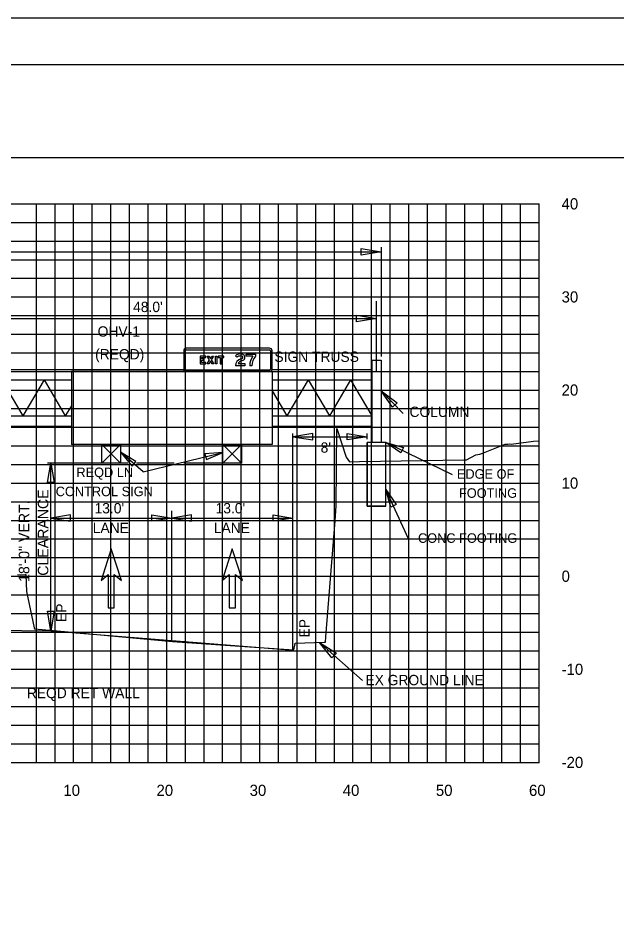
# Model space of a CAD drawing. Extents: x 2193008 to 2198143, y 1236112 to 1237864.
# Drawn here: x 2195392.7 to 2195457, y 1237239.8 to 1237338 of the extents above; entities that cross this region are included whole.
import ezdxf

# ---------------------------------------------------------------- set-up
doc = ezdxf.new("R2010")
doc.units = 0
for name, color, linetype in [('10', 7, 'Continuous'), ('3', 7, 'Continuous'), ('31', 7, 'Continuous'), ('60', 7, 'Continuous'), ('CL-CNST', 7, 'Continuous'), ('GSBWFILL', 7, 'Continuous'), ('GSCOLORFILL', 7, 'Continuous'), ('GSDIMS', 7, 'Continuous'), ('GSOUTLINE', 7, 'Continuous'), ('Level 1', 7, 'Continuous'), ('Level 28', 7, 'Continuous'), ('Level 55', 7, 'Continuous'), ('Level 62', 7, 'Continuous'), ('M-ROADS', 7, 'Continuous'), ('SHT-BDR', 7, 'Continuous'), ('SHT-BNDRY', 7, 'Continuous'), ('V7Level1', 7, 'Continuous')]:
    doc.layers.add(name, color=color, linetype=linetype)

msp = doc.modelspace()

# ---------------------------------------------------------------- linework, layer by layer
msp.add_line((2195431.149, 1237300.108), (2195431.149, 1237307.648))
at = {"layer": '3'}
for p, q in [((2195345.592, 1237312.95), (2195431.649, 1237312.95)), ((2195431.649, 1237313.437), (2195431.649, 1237301.72)), ((2195430.649, 1237301.295), (2195430.649, 1237292.478)), ((2195431.649, 1237301.295), (2195431.649, 1237292.478)), ((2195434.018, 1237295.573), (2195431.649, 1237298.016)), ((2195422.173, 1237270.174), (2195422.173, 1237293.438)), ((2195430.149, 1237292.816), (2195430.149, 1237293.438)), ((2195432.173, 1237292.478), (2195430.149, 1237292.478)), ((2195430.149, 1237285.625), (2195430.149, 1237292.478)), ((2195439.311, 1237289.012), (2195432.173, 1237292.478)), ((2195432.173, 1237285.625), (2195432.173, 1237292.478)), ((2195406.108, 1237289.3), (2195403.67, 1237291.448)), ((2195406.108, 1237289.3), (2195414.672, 1237291.412)), ((2195396.169, 1237272.254), (2195396.169, 1237290.254)), ((2195434.599, 1237282.115), (2195432.173, 1237287.417)), ((2195432.173, 1237285.625), (2195430.149, 1237285.625)), ((2195409.171, 1237271.214), (2195409.171, 1237285.142)), ((2195429.639, 1237266.891), (2195425.039, 1237270.994))]:
    msp.add_line(p, q, dxfattribs=at)
at = {"layer": '60'}
for p, q in [((2195448.632, 1237258.106), (2195448.632, 1237318.106)), ((2195328.632, 1237258.106), (2195448.632, 1237258.106)), ((2195398.632, 1237258.046), (2195398.632, 1237258.106)), ((2195408.632, 1237258.046), (2195408.632, 1237258.106)), ((2195418.632, 1237258.046), (2195418.632, 1237258.106)), ((2195428.632, 1237258.046), (2195428.632, 1237258.106)), ((2195438.632, 1237258.046), (2195438.632, 1237258.106)), ((2195448.632, 1237258.046), (2195448.632, 1237258.106))]:
    msp.add_line(p, q, dxfattribs=at)
at = {"layer": 'CL-CNST'}
msp.add_lwpolyline([(2195389.882, 1237272.317), (2195396.169, 1237272.254), (2195409.171, 1237271.214), (2195422.259, 1237270.167)], dxfattribs=at)
at = {"layer": 'GSBWFILL'}
msp.add_line((2195417.766, 1237300.716), (2195417.541, 1237300.716), dxfattribs=at)
for points in [[(2195417.872, 1237301.74), (2195417.166, 1237301.74), (2195417.166, 1237301.965), (2195418.178, 1237301.965), (2195418.178, 1237301.758)], [(2195416.163, 1237301.624), (2195416.017, 1237301.795)], [(2195416.292, 1237300.941), (2195417.029, 1237300.941), (2195417.029, 1237300.716), (2195416.017, 1237300.716)]]:
    msp.add_lwpolyline(points, dxfattribs=at)
for points in [[(2195412.845, 1237301.074), (2195412.371, 1237301.074), (2195412.371, 1237301.298), (2195412.617, 1237301.298), (2195412.617, 1237301.447), (2195412.371, 1237301.447), (2195412.371, 1237301.607), (2195412.833, 1237301.607), (2195412.833, 1237301.756), (2195412.221, 1237301.756), (2195412.221, 1237300.924), (2195412.845, 1237300.924)], [(2195413.509, 1237300.924), (2195413.324, 1237301.219), (2195413.139, 1237300.924), (2195412.962, 1237300.924), (2195413.236, 1237301.36), (2195412.987, 1237301.756), (2195413.164, 1237301.756), (2195413.324, 1237301.501), (2195413.484, 1237301.756), (2195413.661, 1237301.756), (2195413.413, 1237301.36), (2195413.686, 1237300.924)], [(2195413.853, 1237300.924), (2195413.853, 1237301.756), (2195414.003, 1237301.756), (2195414.003, 1237300.924)], [(2195414.144, 1237301.607), (2195414.381, 1237301.607), (2195414.381, 1237300.924), (2195414.531, 1237300.924), (2195414.531, 1237301.607), (2195414.769, 1237301.607), (2195414.769, 1237301.756), (2195414.144, 1237301.756)]]:
    msp.add_lwpolyline(points, close=True, dxfattribs=at)
for radius, start in [(1.748, 144.14653), (1.523, 136.84518)]:
    msp.add_arc((2195419.289, 1237300.716), radius, start, 180, dxfattribs=at)
for centre, major_axis, start_param, end_param in [((2195416.539, 1237301.181), (0, 0.806), 0, 0.70376), ((2195416.539, 1237301.197), (0, 0.789), 6.02311, 6.283185), ((2195416.624, 1237301.517), (0, 0.458), 5.706931, 6.02311), ((2195416.771, 1237300.716), (0, 0.754), 0.25053, 1.570796), ((2195416.539, 1237301.181), (0, 0.581), 0, 0.70376), ((2195416.771, 1237300.716), (0, 0.529), 0.25053, 1.132058), ((2195416.539, 1237301.197), (0, 0.565), 6.02311, 6.283185), ((2195416.41, 1237302.128), (0, 0.704), 3.392123, 3.626327), ((2195416.41, 1237302.128), (0, 0.928), 3.392123, 3.626327), ((2195416.624, 1237301.517), (0, 0.233), 5.706931, 6.02311), ((2195416.68, 1237301.615), (0, 0.124), 3.626327, 4.712389), ((2195416.687, 1237301.615), (0, 0.117), 4.712389, 5.706931), ((2195416.68, 1237301.615), (0, 0.349), 3.626327, 4.712389), ((2195416.687, 1237301.615), (0, 0.341), 4.712389, 5.706931)]:
    msp.add_ellipse(centre, major_axis=major_axis, ratio=0.999994, start_param=start_param, end_param=end_param, dxfattribs=at)
at = {"layer": 'GSCOLORFILL'}
for p, q in [((2195410.452, 1237302.322), (2195410.452, 1237300.358)), ((2195410.619, 1237300.358), (2195410.619, 1237302.322)), ((2195419.68, 1237302.593), (2195410.723, 1237302.593)), ((2195410.723, 1237302.427), (2195419.68, 1237302.427)), ((2195419.784, 1237302.322), (2195419.784, 1237300.358)), ((2195419.951, 1237300.358), (2195419.951, 1237302.322)), ((2195410.723, 1237300.087), (2195410.723, 1237300.254)), ((2195419.68, 1237300.254), (2195410.724, 1237300.254)), ((2195410.724, 1237300.254), (2195410.724, 1237300.087)), ((2195410.724, 1237300.087), (2195419.68, 1237300.087)), ((2195417.766, 1237300.716), (2195417.541, 1237300.716))]:
    msp.add_line(p, q, dxfattribs=at)
for points in [[(2195417.872, 1237301.74), (2195417.166, 1237301.74), (2195417.166, 1237301.965), (2195418.178, 1237301.965), (2195418.178, 1237301.758)], [(2195416.163, 1237301.624), (2195416.017, 1237301.795)], [(2195416.292, 1237300.941), (2195417.029, 1237300.941), (2195417.029, 1237300.716), (2195416.017, 1237300.716)]]:
    msp.add_lwpolyline(points, dxfattribs=at)
for points in [[(2195412.845, 1237301.074), (2195412.371, 1237301.074), (2195412.371, 1237301.298), (2195412.617, 1237301.298), (2195412.617, 1237301.447), (2195412.371, 1237301.447), (2195412.371, 1237301.607), (2195412.833, 1237301.607), (2195412.833, 1237301.756), (2195412.221, 1237301.756), (2195412.221, 1237300.924), (2195412.845, 1237300.924)], [(2195413.509, 1237300.924), (2195413.324, 1237301.219), (2195413.139, 1237300.924), (2195412.962, 1237300.924), (2195413.236, 1237301.36), (2195412.987, 1237301.756), (2195413.164, 1237301.756), (2195413.324, 1237301.501), (2195413.484, 1237301.756), (2195413.661, 1237301.756), (2195413.413, 1237301.36), (2195413.686, 1237300.924)], [(2195413.853, 1237300.924), (2195413.853, 1237301.756), (2195414.003, 1237301.756), (2195414.003, 1237300.924)], [(2195414.144, 1237301.607), (2195414.381, 1237301.607), (2195414.381, 1237300.924), (2195414.531, 1237300.924), (2195414.531, 1237301.607), (2195414.769, 1237301.607), (2195414.769, 1237301.756), (2195414.144, 1237301.756)]]:
    msp.add_lwpolyline(points, close=True, dxfattribs=at)
for centre, radius, start, end in [((2195410.723, 1237302.322), 0.271, 90, 180), ((2195410.723, 1237302.322), 0.104, 90, 180), ((2195419.68, 1237302.322), 0.271, 0, 90), ((2195419.68, 1237302.322), 0.104, 0, 90), ((2195419.289, 1237300.716), 1.748, 144.14653, 180), ((2195419.289, 1237300.716), 1.523, 136.84518, 180), ((2195410.723, 1237300.358), 0.271, 180, 270), ((2195410.723, 1237300.358), 0.104, 180, 270), ((2195419.68, 1237300.358), 0.271, 270, 0), ((2195419.68, 1237300.358), 0.104, 270, 0)]:
    msp.add_arc(centre, radius, start, end, dxfattribs=at)
for centre, major_axis, start_param, end_param in [((2195416.539, 1237301.181), (0, 0.806), 0, 0.70376), ((2195416.539, 1237301.197), (0, 0.789), 6.02311, 6.283185), ((2195416.624, 1237301.517), (0, 0.458), 5.706931, 6.02311), ((2195416.771, 1237300.716), (0, 0.754), 0.25053, 1.570796), ((2195416.539, 1237301.181), (0, 0.581), 0, 0.70376), ((2195416.771, 1237300.716), (0, 0.529), 0.25053, 1.132058), ((2195416.539, 1237301.197), (0, 0.565), 6.02311, 6.283185), ((2195416.41, 1237302.128), (0, 0.704), 3.392123, 3.626327), ((2195416.41, 1237302.128), (0, 0.928), 3.392123, 3.626327), ((2195416.624, 1237301.517), (0, 0.233), 5.706931, 6.02311), ((2195416.68, 1237301.615), (0, 0.124), 3.626327, 4.712389), ((2195416.687, 1237301.615), (0, 0.117), 4.712389, 5.706931), ((2195416.68, 1237301.615), (0, 0.349), 3.626327, 4.712389), ((2195416.687, 1237301.615), (0, 0.341), 4.712389, 5.706931)]:
    msp.add_ellipse(centre, major_axis=major_axis, ratio=0.999994, start_param=start_param, end_param=end_param, dxfattribs=at)
at = {"layer": 'GSDIMS'}
for p, q in [((2195383.079, 1237305.791), (2195431.143, 1237305.791)), ((2195430.649, 1237301.295), (2195431.649, 1237301.295)), ((2195383.079, 1237300.295), (2195410.452, 1237300.295)), ((2195398.387, 1237300.087), (2195398.387, 1237292.254)), ((2195419.951, 1237300.087), (2195398.387, 1237300.087)), ((2195419.951, 1237300.295), (2195430.649, 1237300.295)), ((2195419.951, 1237300.087), (2195419.951, 1237292.254)), ((2195383.079, 1237299.184), (2195398.387, 1237299.184)), ((2195390.903, 1237299.184), (2195393.181, 1237295.322)), ((2195395.46, 1237299.184), (2195393.181, 1237295.322)), ((2195395.46, 1237299.184), (2195397.738, 1237295.322)), ((2195419.951, 1237299.184), (2195430.649, 1237299.184)), ((2195423.813, 1237299.184), (2195421.534, 1237295.322)), ((2195423.813, 1237299.184), (2195426.092, 1237295.322)), ((2195428.37, 1237299.184), (2195426.092, 1237295.322)), ((2195428.37, 1237299.184), (2195430.649, 1237295.322)), ((2195419.951, 1237298.006), (2195421.534, 1237295.322)), ((2195398.387, 1237296.421), (2195397.738, 1237295.322)), ((2195383.079, 1237295.322), (2195398.387, 1237295.322)), ((2195419.951, 1237295.322), (2195430.649, 1237295.322)), ((2195383.058, 1237294.211), (2195398.387, 1237294.211)), ((2195419.951, 1237294.211), (2195430.649, 1237294.211)), ((2195422.177, 1237293.091), (2195430.149, 1237293.091)), ((2195419.951, 1237292.254), (2195398.387, 1237292.254)), ((2195404.441, 1237290.254), (2195395.814, 1237290.254)), ((2195409.415, 1237290.254), (2195405.378, 1237290.254)), ((2195414.672, 1237290.254), (2195410.467, 1237290.254)), ((2195396.169, 1237284.354), (2195409.171, 1237284.354)), ((2195409.171, 1237284.354), (2195422.173, 1237284.354))]:
    msp.add_line(p, q, dxfattribs=at)
for points in [[(2195431.649, 1237312.95), (2195429.52, 1237312.603), (2195429.52, 1237313.298)], [(2195431.143, 1237305.791), (2195429.014, 1237305.444), (2195429.014, 1237306.139)], [(2195431.649, 1237298.016), (2195433.371, 1237296.744), (2195432.857, 1237296.266)], [(2195422.177, 1237293.091), (2195424.305, 1237292.743), (2195424.305, 1237293.438)], [(2195430.149, 1237293.091), (2195428.02, 1237292.743), (2195428.02, 1237293.438)], [(2195432.173, 1237292.478), (2195434.042, 1237291.926), (2195433.762, 1237291.35)], [(2195403.67, 1237291.448), (2195404.9, 1237289.937), (2195405.324, 1237290.418)], [(2195414.672, 1237291.412), (2195412.729, 1237291.263), (2195412.883, 1237290.641)], [(2195396.169, 1237290.254), (2195396.524, 1237288.171), (2195395.814, 1237288.171)], [(2195432.173, 1237287.417), (2195433.264, 1237285.802), (2195432.682, 1237285.536)], [(2195396.169, 1237284.354), (2195398.297, 1237284.006), (2195398.297, 1237284.701)], [(2195409.171, 1237284.354), (2195407.043, 1237284.006), (2195407.043, 1237284.701)], [(2195409.171, 1237284.354), (2195411.299, 1237284.006), (2195411.299, 1237284.701)], [(2195422.173, 1237284.354), (2195420.045, 1237284.006), (2195420.045, 1237284.701)], [(2195396.169, 1237272.254), (2195395.814, 1237274.337), (2195396.524, 1237274.337)], [(2195425.039, 1237270.994), (2195426.849, 1237269.85), (2195426.37, 1237269.336)]]:
    msp.add_lwpolyline(points, close=True, dxfattribs=at)
at = {"layer": 'GSOUTLINE'}
msp.add_line((2195417.766, 1237300.716), (2195417.541, 1237300.716), dxfattribs=at)
for points in [[(2195417.872, 1237301.74), (2195417.166, 1237301.74), (2195417.166, 1237301.965), (2195418.178, 1237301.965), (2195418.178, 1237301.758)], [(2195416.163, 1237301.624), (2195416.017, 1237301.795)], [(2195416.292, 1237300.941), (2195417.029, 1237300.941), (2195417.029, 1237300.716), (2195416.017, 1237300.716)]]:
    msp.add_lwpolyline(points, dxfattribs=at)
for points in [[(2195412.845, 1237301.074), (2195412.371, 1237301.074), (2195412.371, 1237301.298), (2195412.617, 1237301.298), (2195412.617, 1237301.447), (2195412.371, 1237301.447), (2195412.371, 1237301.607), (2195412.833, 1237301.607), (2195412.833, 1237301.756), (2195412.221, 1237301.756), (2195412.221, 1237300.924), (2195412.845, 1237300.924)], [(2195413.509, 1237300.924), (2195413.324, 1237301.219), (2195413.139, 1237300.924), (2195412.962, 1237300.924), (2195413.236, 1237301.36), (2195412.987, 1237301.756), (2195413.164, 1237301.756), (2195413.324, 1237301.501), (2195413.484, 1237301.756), (2195413.661, 1237301.756), (2195413.413, 1237301.36), (2195413.686, 1237300.924)], [(2195413.853, 1237300.924), (2195413.853, 1237301.756), (2195414.003, 1237301.756), (2195414.003, 1237300.924)], [(2195414.144, 1237301.607), (2195414.381, 1237301.607), (2195414.381, 1237300.924), (2195414.531, 1237300.924), (2195414.531, 1237301.607), (2195414.769, 1237301.607), (2195414.769, 1237301.756), (2195414.144, 1237301.756)]]:
    msp.add_lwpolyline(points, close=True, dxfattribs=at)
for radius, start in [(1.748, 144.14653), (1.523, 136.84518)]:
    msp.add_arc((2195419.289, 1237300.716), radius, start, 180, dxfattribs=at)
for centre, major_axis, start_param, end_param in [((2195416.539, 1237301.181), (0, 0.806), 0, 0.70376), ((2195416.539, 1237301.197), (0, 0.789), 6.02311, 6.283185), ((2195416.624, 1237301.517), (0, 0.458), 5.706931, 6.02311), ((2195416.771, 1237300.716), (0, 0.754), 0.25053, 1.570796), ((2195416.539, 1237301.181), (0, 0.581), 0, 0.70376), ((2195416.771, 1237300.716), (0, 0.529), 0.25053, 1.132058), ((2195416.539, 1237301.197), (0, 0.565), 6.02311, 6.283185), ((2195416.41, 1237302.128), (0, 0.704), 3.392123, 3.626327), ((2195416.41, 1237302.128), (0, 0.928), 3.392123, 3.626327), ((2195416.624, 1237301.517), (0, 0.233), 5.706931, 6.02311), ((2195416.68, 1237301.615), (0, 0.124), 3.626327, 4.712389), ((2195416.687, 1237301.615), (0, 0.117), 4.712389, 5.706931), ((2195416.68, 1237301.615), (0, 0.349), 3.626327, 4.712389), ((2195416.687, 1237301.615), (0, 0.341), 4.712389, 5.706931)]:
    msp.add_ellipse(centre, major_axis=major_axis, ratio=0.999994, start_param=start_param, end_param=end_param, dxfattribs=at)
at = {"layer": 'Level 1'}
for p, q in [((2195401.67, 1237292.254), (2195403.67, 1237290.254)), ((2195403.67, 1237292.254), (2195401.67, 1237290.254)), ((2195414.672, 1237292.254), (2195416.672, 1237290.254)), ((2195414.672, 1237290.254), (2195416.672, 1237292.254))]:
    msp.add_line(p, q, dxfattribs=at)
for points in [[(2195401.67, 1237292.254), (2195403.67, 1237292.254), (2195403.67, 1237290.254), (2195401.67, 1237290.254)], [(2195414.672, 1237292.254), (2195416.672, 1237292.254), (2195416.672, 1237290.254), (2195414.672, 1237290.254)]]:
    msp.add_lwpolyline(points, close=True, dxfattribs=at)
at = {"layer": 'Level 28'}
for p, q in [((2195402.67, 1237281.044), (2195401.581, 1237277.646)), ((2195403.759, 1237277.646), (2195402.67, 1237281.044)), ((2195415.672, 1237281.044), (2195414.583, 1237277.646)), ((2195416.761, 1237277.646), (2195415.672, 1237281.044)), ((2195401.581, 1237277.646), (2195402.343, 1237278.285)), ((2195402.343, 1237278.285), (2195402.343, 1237274.714)), ((2195402.997, 1237274.714), (2195402.997, 1237278.285)), ((2195402.997, 1237278.285), (2195403.759, 1237277.646)), ((2195414.583, 1237277.646), (2195415.345, 1237278.285)), ((2195415.345, 1237278.285), (2195415.345, 1237274.714)), ((2195415.999, 1237274.714), (2195415.999, 1237278.285)), ((2195415.999, 1237278.285), (2195416.761, 1237277.646)), ((2195402.343, 1237274.714), (2195402.997, 1237274.714)), ((2195415.345, 1237274.714), (2195415.999, 1237274.714))]:
    msp.add_line(p, q, dxfattribs=at)
at = {"layer": 'Level 62'}
for p, q in [((2195328.632, 1237318.106), (2195448.632, 1237318.106)), ((2195394.632, 1237258.106), (2195394.632, 1237318.106)), ((2195396.632, 1237258.106), (2195396.632, 1237318.106)), ((2195398.632, 1237258.106), (2195398.632, 1237318.106)), ((2195400.632, 1237258.106), (2195400.632, 1237318.106)), ((2195402.632, 1237258.106), (2195402.632, 1237318.106)), ((2195404.632, 1237258.106), (2195404.632, 1237318.106)), ((2195406.632, 1237258.106), (2195406.632, 1237318.106)), ((2195408.632, 1237258.106), (2195408.632, 1237318.106)), ((2195410.632, 1237258.106), (2195410.632, 1237318.106)), ((2195412.632, 1237258.106), (2195412.632, 1237318.106)), ((2195414.632, 1237258.106), (2195414.632, 1237318.106)), ((2195416.632, 1237258.106), (2195416.632, 1237318.106)), ((2195418.632, 1237258.106), (2195418.632, 1237318.106)), ((2195420.632, 1237258.106), (2195420.632, 1237318.106)), ((2195422.632, 1237258.106), (2195422.632, 1237318.106)), ((2195424.632, 1237258.106), (2195424.632, 1237318.106)), ((2195426.632, 1237258.106), (2195426.632, 1237318.106)), ((2195428.632, 1237258.106), (2195428.632, 1237318.106)), ((2195430.632, 1237258.106), (2195430.632, 1237318.106)), ((2195432.632, 1237258.106), (2195432.632, 1237318.106)), ((2195434.632, 1237258.106), (2195434.632, 1237318.106)), ((2195436.632, 1237258.106), (2195436.632, 1237318.106)), ((2195438.632, 1237258.106), (2195438.632, 1237318.106)), ((2195440.632, 1237258.106), (2195440.632, 1237318.106)), ((2195442.632, 1237258.106), (2195442.632, 1237318.106)), ((2195444.632, 1237258.106), (2195444.632, 1237318.106)), ((2195446.632, 1237258.106), (2195446.632, 1237318.106)), ((2195448.632, 1237258.106), (2195448.632, 1237318.106)), ((2195328.632, 1237316.106), (2195448.632, 1237316.106)), ((2195328.632, 1237314.106), (2195448.632, 1237314.106)), ((2195328.632, 1237312.106), (2195448.632, 1237312.106)), ((2195328.632, 1237310.106), (2195448.632, 1237310.106)), ((2195328.632, 1237308.106), (2195448.632, 1237308.106)), ((2195328.632, 1237306.106), (2195448.632, 1237306.106)), ((2195328.632, 1237304.106), (2195448.632, 1237304.106)), ((2195328.632, 1237302.106), (2195448.632, 1237302.106)), ((2195328.632, 1237300.106), (2195448.632, 1237300.106)), ((2195328.632, 1237298.106), (2195448.632, 1237298.106)), ((2195328.632, 1237296.106), (2195448.632, 1237296.106)), ((2195328.632, 1237294.106), (2195448.632, 1237294.106)), ((2195328.632, 1237292.106), (2195448.632, 1237292.106)), ((2195328.632, 1237290.106), (2195448.632, 1237290.106)), ((2195328.632, 1237288.106), (2195448.632, 1237288.106)), ((2195328.632, 1237286.106), (2195448.632, 1237286.106)), ((2195328.632, 1237284.106), (2195448.632, 1237284.106)), ((2195328.632, 1237282.106), (2195448.632, 1237282.106)), ((2195328.632, 1237280.106), (2195448.632, 1237280.106)), ((2195328.632, 1237278.106), (2195448.632, 1237278.106)), ((2195328.632, 1237276.106), (2195448.632, 1237276.106)), ((2195328.632, 1237274.106), (2195448.632, 1237274.106)), ((2195328.632, 1237272.106), (2195448.632, 1237272.106)), ((2195328.632, 1237270.106), (2195448.632, 1237270.106)), ((2195328.632, 1237268.106), (2195448.632, 1237268.106)), ((2195328.632, 1237266.106), (2195448.632, 1237266.106)), ((2195328.632, 1237264.106), (2195448.632, 1237264.106)), ((2195328.632, 1237262.106), (2195448.632, 1237262.106)), ((2195328.632, 1237260.106), (2195448.632, 1237260.106)), ((2195328.632, 1237258.106), (2195448.632, 1237258.106))]:
    msp.add_line(p, q, dxfattribs=at)
msp.add_lwpolyline([(2195203.786, 1237118.036), (2195543.786, 1237118.036), (2195543.786, 1237338.036), (2195203.786, 1237338.036)], close=True, dxfattribs=at)
at = {"layer": 'M-ROADS'}
msp.add_lwpolyline([(2195392.603, 1237278.286), (2195392.945, 1237278.255), (2195393.445, 1237278.292), (2195393.474, 1237278.294), (2195393.494, 1237278.296), (2195393.496, 1237278.256), (2195393.567, 1237276.459), (2195394.395, 1237272.547), (2195394.414, 1237272.457), (2195397.263, 1237272.193), (2195409.251, 1237271.081), (2195418.556, 1237270.454), (2195422.267, 1237270.204), (2195422.417, 1237270.886), (2195422.422, 1237270.914), (2195425.552, 1237271.01), (2195425.683, 1237271.014), (2195425.685, 1237271.038), (2195425.733, 1237271.587), (2195426.729, 1237284.052), (2195426.818, 1237285.656), (2195426.887, 1237293.963), (2195427.905, 1237290.896), (2195428.272, 1237290.401), (2195429.339, 1237290.433), (2195440.521, 1237290.607), (2195440.761, 1237290.61), (2195440.831, 1237290.609), (2195441.819, 1237291.14), (2195442.24, 1237291.223), (2195442.48, 1237291.27), (2195444.987, 1237292.304), (2195445.258, 1237292.306), (2195445.393, 1237292.308), (2195445.618, 1237292.306), (2195448.025, 1237292.595), (2195448.632, 1237292.642)], dxfattribs=at)
at = {"layer": 'SHT-BDR'}
msp.add_lwpolyline([(2195228.783, 1237133.046), (2195528.783, 1237133.046), (2195528.783, 1237323.046), (2195228.783, 1237323.046)], close=True, dxfattribs=at)
at = {"layer": 'SHT-BNDRY'}
msp.add_lwpolyline([(2195216.286, 1237123.036), (2195538.786, 1237123.036), (2195538.786, 1237333.036), (2195216.286, 1237333.036)], close=True, dxfattribs=at)
at = {"layer": 'V7Level1'}
msp.add_lwpolyline([(2195430.149, 1237285.625), (2195432.173, 1237285.625), (2195432.173, 1237292.478), (2195430.149, 1237292.478)], close=True, dxfattribs=at)

# ---------------------------------------------------------------- texts
at = {"layer": '10'}
for s, p in [('10', (2195397.532, 1237254.506)), ('20', (2195407.532, 1237254.506)), ('30', (2195417.532, 1237254.506)), ('40', (2195427.532, 1237254.506)), ('50', (2195437.532, 1237254.506)), ('60', (2195447.532, 1237254.506))]:
    msp.add_text(s, height=1.2, dxfattribs=at).set_placement(p)
at = {"layer": '31'}
for s, p in [('40', (2195451.032, 1237317.506)), ('30', (2195451.032, 1237307.506)), ('20', (2195451.032, 1237297.506)), ('10', (2195451.032, 1237287.506)), ('0', (2195451.032, 1237277.506)), ('-10', (2195451.032, 1237267.506)), ('-20', (2195451.032, 1237257.506))]:
    msp.add_text(s, height=1.2, dxfattribs=at).set_placement(p)
at = {"layer": 'Level 55'}
for s, height, p in [("48.0'", 1.1105, (2195405.023, 1237306.48)), ('OHV-1', 1.1105, (2195401.212, 1237303.84)), ('(REQD)', 1.1105, (2195400.94, 1237301.397)), ('SIGN TRUSS', 1.1105, (2195420.191, 1237301.128)), ('COLUMN', 1.1105, (2195434.7, 1237295.21)), ("8'", 1.1105, (2195425.158, 1237291.371)), ('REQD LN', 1.0246, (2195398.93, 1237288.75)), ('EDGE OF', 1.0246, (2195439.788, 1237288.576)), ('CONTROL SIGN', 1.02464, (2195396.707, 1237286.701)), ('FOOTING', 1.0246, (2195440.013, 1237286.527)), ("13.0'", 1.1105, (2195400.877, 1237284.854)), ("13.0'", 1.1105, (2195413.879, 1237284.854)), ('LANE', 1.1105, (2195400.684, 1237282.743)), ('LANE', 1.1105, (2195413.686, 1237282.743)), ('CONC FOOTING', 1.02464, (2195435.612, 1237281.69)), ('EX GROUND LINE', 1.11046, (2195429.966, 1237266.394))]:
    msp.add_text(s, height=height, dxfattribs=at).set_placement(p)
for s, height, rotation, p in [('CLEARANCE', 1.1346, 90, (2195395.917, 1237278.158)), ('18\'-0" VERT.', 1.13464, 90, (2195393.875, 1237277.492)), ('EP', 1.1105, 90, (2195397.86, 1237273.189)), ('EP', 1.1105, 90, (2195423.963, 1237271.525)), ('REQD RET WALL', 1.11046, 360, (2195393.608, 1237265.003))]:
    msp.add_text(s, height=height, rotation=rotation, dxfattribs=at).set_placement(p)

doc.saveas('drawing.dxf')
